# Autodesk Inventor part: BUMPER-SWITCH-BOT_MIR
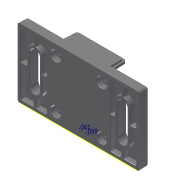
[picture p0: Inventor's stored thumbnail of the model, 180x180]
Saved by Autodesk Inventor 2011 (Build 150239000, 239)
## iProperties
Created: 2007-08
Part Number: BUMPER-SWITCH-BOT_MIR
Material: ABS Plastic
Document SubType Name: Modeling
Density: 1.06 g/cm^3
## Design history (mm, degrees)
derived "BUMPER-SWITCH-BOT.ipt"
sketch "Sketch1"
  geometry: L1 (35.542, 8.536)-(35.717, 3.509) reference; L2 (16.458, 9.501)-(34.542, 9.501) reference; L3 (15.283, 3.509)-(15.459, 8.536) reference; L4 (0.061, 3.509)-(15.283, 3.509) reference; L5 (0, 0)-(0.061, 3.509) reference; L6 (0, 0)-(51, 0) reference; L7 (50.939, 3.509)-(51, 0) reference; L8 (35.717, 3.509)-(50.939, 3.509) reference; L9 (28.55, 2.014)-(28.55, 2.814) reference; L10 (23.75, 0.714)-(27.25, 0.714) reference; L11 (22.45, 2.814)-(22.45, 2.014) reference; L12 (27.25, 4.115)-(23.75, 4.115) reference; L13 (28.55, 2.414)-(22.45, 2.414); 3 further points
  constraints: 3 midpoint, 2 end point, 2 point on line, 6 other
  dimensions: "d1" = 1.5494 distance from line of point (27.001, 2.414) L9; "d2" = 1.4986 distance of point (24.002, 2.414) point (25.5, 2.414)
node "1"
node "2"
node "3"
workplane "Work Plane1"
workplane "Work Plane2"
sketch "Sketch4"
  geometry: 1 further point
workpoint "Work Point4"
sketch "Sketch5"
  geometry: 1 further point
workpoint "Work Point5"
body "Solid1"
tag "TaggingFeature2"
feature "DerivedBody::BUMPER-SWITCH-BOT.ipt" dims "d0" = 10
other parameters: "d3" = 6.35, "d4" = 12.7
